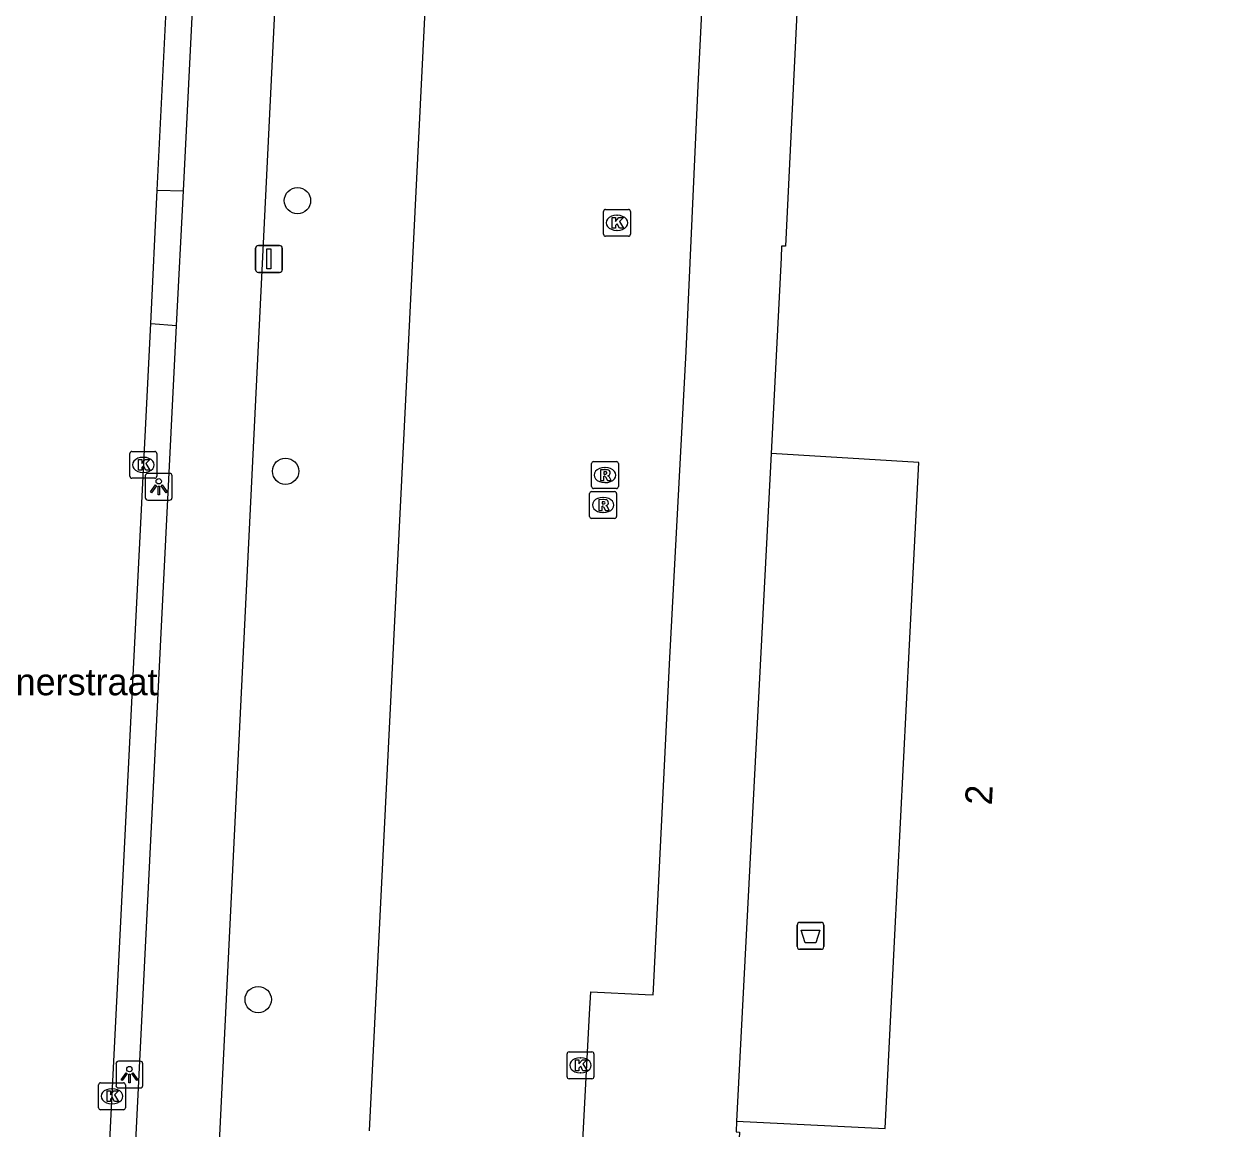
# Model space of a CAD drawing. Extents: x 161761 to 162722, y 384793 to 385405.
# Drawn here: x 162110.58 to 162155.63, y 384928.4 to 384969.48 of the extents above; entities that cross this region are included whole.
import ezdxf

# ---------------------------------------------------------------- set-up
doc = ezdxf.new("R2010")
doc.units = 0
for name, color, linetype in [('IMGEO_Afvalbak', 7, 'Continuous'), ('IMGEO_Boom', 7, 'Continuous'), ('IMGEO_Fietspad_gesloten', 7, 'Continuous'), ('IMGEO_Kolk', 7, 'Continuous'), ('IMGEO_Lichtpunt', 7, 'Continuous'), ('IMGEO_Openbare_ruimte_label', 7, 'Continuous'), ('IMGEO_Pand', 7, 'Continuous'), ('IMGEO_Pand_nummerreeks', 7, 'Continuous'), ('IMGEO_Rijbaan_lokaal_gesloten', 7, 'Continuous'), ('IMGEO_Rijbaan_lokaal_open', 7, 'Continuous'), ('IMGEO_Rioolput', 7, 'Continuous'), ('IMGEO_Verkeersbordpaal', 7, 'Continuous'), ('IMGEO_Verkeerseiland_open', 7, 'Continuous'), ('IMGEO_Voetpad_open', 7, 'Continuous')]:
    doc.layers.add(name, color=color, linetype=linetype)

msp = doc.modelspace()

# ---------------------------------------------------------------- linework, layer by layer
at = {"layer": 'IMGEO_Afvalbak'}
for p, q in [((162139.32, 384935.172), (162139.32, 384935.972)), ((162139.32, 384935.972), (162139.32, 384935.172)), ((162139.42, 384936.072), (162140.21, 384936.072)), ((162140.21, 384936.072), (162139.42, 384936.072)), ((162140.31, 384935.972), (162140.31, 384935.172)), ((162140.31, 384935.172), (162140.31, 384935.972)), ((162140.21, 384935.072), (162139.42, 384935.072)), ((162139.42, 384935.072), (162140.21, 384935.072))]:
    msp.add_line(p, q, dxfattribs=at)
msp.add_lwpolyline([(162139.463, 384935.786), (162140.167, 384935.786), (162140.018, 384935.316), (162139.612, 384935.316), (162139.463, 384935.786)], dxfattribs=at)
for centre, start, end in [((162139.42, 384935.972), 90, 180), ((162139.42, 384935.972), 90, 180), ((162140.21, 384935.972), 0, 90), ((162140.21, 384935.972), 360, 90), ((162139.42, 384935.172), 180, 270), ((162139.42, 384935.172), 180, 270), ((162140.21, 384935.172), 270, 0), ((162140.21, 384935.172), 270, 0)]:
    msp.add_arc(centre, 0.1, start, end, dxfattribs=at)
at = {"layer": 'IMGEO_Boom'}
for centre in [(162120.741, 384962.917), (162120.301, 384952.853), (162119.282, 384933.201)]:
    msp.add_circle(centre, 0.489, dxfattribs=at)
at = {"layer": 'IMGEO_Fietspad_gesloten'}
for points in [[(162116.503, 384963.282), (162118.683, 385007.076)], [(162120.83, 384989.204), (162116.127, 384893.203)], [(162116.239, 384958.276), (162116.503, 384963.282)], [(162112.494, 384887.839), (162113.167, 384887.939), (162113.123, 384894.953), (162113.284, 384898.832), (162116.239, 384958.276)]]:
    msp.add_lwpolyline(points, dxfattribs=at)
at = {"layer": 'IMGEO_Kolk'}
for p, q in [((162132.121, 384961.666), (162132.121, 384962.518)), ((162132.196, 384962.592), (162133.048, 384962.592)), ((162133.122, 384962.518), (162133.122, 384961.666)), ((162132.609, 384962.372), (162132.634, 384962.372)), ((162133.048, 384961.592), (162132.196, 384961.592)), ((162132.632, 384961.812), (162132.607, 384961.812)), ((162114.511, 384952.664), (162114.511, 384953.516)), ((162114.586, 384953.59), (162115.438, 384953.59)), ((162115.512, 384953.516), (162115.512, 384952.664)), ((162114.999, 384953.37), (162115.024, 384953.37)), ((162115.438, 384952.59), (162114.586, 384952.59)), ((162115.022, 384952.81), (162114.997, 384952.81)), ((162130.763, 384930.332), (162130.763, 384931.184)), ((162130.838, 384931.258), (162131.69, 384931.258)), ((162131.251, 384931.038), (162131.276, 384931.038)), ((162131.764, 384931.184), (162131.764, 384930.332)), ((162113.42, 384930.106), (162114.272, 384930.106)), ((162131.69, 384930.258), (162130.838, 384930.258)), ((162131.274, 384930.478), (162131.249, 384930.478)), ((162113.345, 384929.18), (162113.345, 384930.032)), ((162113.833, 384929.886), (162113.858, 384929.886)), ((162114.346, 384930.032), (162114.346, 384929.18)), ((162113.856, 384929.326), (162113.831, 384929.326)), ((162114.272, 384929.106), (162113.42, 384929.106))]:
    msp.add_line(p, q, dxfattribs=at)
for points in [[(162132.121, 384961.666), (162132.121, 384962.518)], [(162132.196, 384962.592), (162133.048, 384962.592)], [(162133.122, 384962.518), (162133.122, 384961.666)], [(162132.442, 384962.292), (162132.565, 384962.292), (162132.565, 384962.141), (162132.695, 384962.292), (162132.859, 384962.292), (162132.713, 384962.141), (162132.866, 384961.892), (162132.714, 384961.892), (162132.629, 384962.056), (162132.565, 384961.989), (162132.565, 384961.892), (162132.442, 384961.892), (162132.442, 384962.292)], [(162133.048, 384961.592), (162132.196, 384961.592)], [(162114.511, 384952.664), (162114.511, 384953.516)], [(162114.586, 384953.59), (162115.438, 384953.59)], [(162115.512, 384953.516), (162115.512, 384952.664)], [(162114.832, 384953.29), (162114.955, 384953.29), (162114.955, 384953.139), (162115.085, 384953.29), (162115.249, 384953.29), (162115.103, 384953.139), (162115.256, 384952.89), (162115.104, 384952.89), (162115.019, 384953.054), (162114.955, 384952.987), (162114.955, 384952.89), (162114.832, 384952.89), (162114.832, 384953.29)], [(162115.438, 384952.59), (162114.586, 384952.59)], [(162130.763, 384930.332), (162130.763, 384931.184)], [(162130.838, 384931.258), (162131.69, 384931.258)], [(162131.084, 384930.958), (162131.207, 384930.958), (162131.207, 384930.807), (162131.337, 384930.958), (162131.501, 384930.958), (162131.355, 384930.807), (162131.508, 384930.558), (162131.356, 384930.558), (162131.271, 384930.722), (162131.207, 384930.655), (162131.207, 384930.558), (162131.084, 384930.558), (162131.084, 384930.958)], [(162131.764, 384931.184), (162131.764, 384930.332)], [(162113.42, 384930.106), (162114.272, 384930.106)], [(162131.69, 384930.258), (162130.838, 384930.258)], [(162113.345, 384929.18), (162113.345, 384930.032)], [(162113.666, 384929.806), (162113.789, 384929.806), (162113.789, 384929.655), (162113.919, 384929.806), (162114.083, 384929.806), (162113.937, 384929.655), (162114.09, 384929.406), (162113.938, 384929.406), (162113.853, 384929.57), (162113.789, 384929.503), (162113.789, 384929.406), (162113.666, 384929.406), (162113.666, 384929.806)], [(162114.346, 384930.032), (162114.346, 384929.18)], [(162114.272, 384929.106), (162113.42, 384929.106)]]:
    msp.add_lwpolyline(points, dxfattribs=at)
for centre, start, end in [((162132.198, 384962.516), 91.552, 178.448), ((162132.198, 384962.516), 91.552, 178.448), ((162133.046, 384962.516), 1.552, 88.448), ((162133.046, 384962.516), 1.552, 88.448), ((162132.198, 384961.668), 181.552, 268.448), ((162132.198, 384961.668), 181.552, 268.448), ((162133.046, 384961.668), 271.552, 358.448), ((162133.046, 384961.668), 271.552, 358.448), ((162114.588, 384953.514), 91.552, 178.448), ((162114.588, 384953.514), 91.552, 178.448), ((162115.436, 384953.514), 1.552, 88.448), ((162115.436, 384953.514), 1.552, 88.448), ((162114.588, 384952.666), 181.552, 268.448), ((162114.588, 384952.666), 181.552, 268.448), ((162115.436, 384952.666), 271.552, 358.448), ((162115.436, 384952.666), 271.552, 358.448), ((162130.84, 384931.182), 91.552, 178.448), ((162130.84, 384931.182), 91.552, 178.448), ((162131.688, 384931.182), 1.552, 88.448), ((162131.688, 384931.182), 1.552, 88.448), ((162113.422, 384930.03), 91.552, 178.448), ((162113.422, 384930.03), 91.552, 178.448), ((162114.27, 384930.03), 1.552, 88.448), ((162114.27, 384930.03), 1.552, 88.448), ((162130.84, 384930.334), 181.552, 268.448), ((162130.84, 384930.334), 181.552, 268.448), ((162131.688, 384930.334), 271.552, 358.448), ((162131.688, 384930.334), 271.552, 358.448), ((162113.422, 384929.182), 181.552, 268.448), ((162113.422, 384929.182), 181.552, 268.448), ((162114.27, 384929.182), 271.552, 358.448), ((162114.27, 384929.182), 271.552, 358.448)]:
    msp.add_arc(centre, 0.0765, start, end, dxfattribs=at)
for centre, major_axis, ratio, start_param, end_param in [((162132.608, 384962.092), (-0.387, 0.002), 0.722429, 4.712389, 7.853982), ((162132.633, 384962.092), (-0.39, 0.002), 0.717154, 1.570796, 4.712389), ((162114.998, 384953.09), (-0.387, 0.002), 0.722429, 4.712389, 7.853982), ((162115.023, 384953.09), (-0.39, 0.002), 0.717154, 1.570796, 4.712389), ((162131.25, 384930.758), (-0.387, 0.002), 0.722429, 4.712389, 7.853982), ((162131.275, 384930.758), (-0.39, 0.002), 0.717154, 1.570796, 4.712389), ((162113.832, 384929.606), (-0.387, 0.002), 0.722429, 4.712389, 7.853982), ((162113.857, 384929.606), (-0.39, 0.002), 0.717154, 1.570796, 4.712389)]:
    msp.add_ellipse(centre, major_axis=major_axis, ratio=ratio, start_param=start_param, end_param=end_param, dxfattribs=at)
at = {"layer": 'IMGEO_Lichtpunt'}
for p, q in [((162115.085, 384952.68), (162115.085, 384951.873)), ((162115.085, 384952.68), (162115.085, 384951.873)), ((162115.987, 384952.775), (162115.179, 384952.775)), ((162115.987, 384952.775), (162115.179, 384952.775)), ((162116.081, 384951.873), (162116.081, 384952.68)), ((162116.081, 384951.873), (162116.081, 384952.68)), ((162115.179, 384951.779), (162115.987, 384951.779)), ((162115.179, 384951.779), (162115.987, 384951.779)), ((162113.995, 384930.818), (162113.995, 384930.011)), ((162113.995, 384930.818), (162113.995, 384930.011)), ((162114.897, 384930.913), (162114.089, 384930.913)), ((162114.897, 384930.913), (162114.089, 384930.913)), ((162114.991, 384930.011), (162114.991, 384930.818)), ((162114.991, 384930.011), (162114.991, 384930.818)), ((162114.089, 384929.917), (162114.897, 384929.917)), ((162114.089, 384929.917), (162114.897, 384929.917))]:
    msp.add_line(p, q, dxfattribs=at)
for points in [[(162115.459, 384952.344), (162115.498, 384952.316), (162115.31, 384952.054), (162115.272, 384952.081), (162115.459, 384952.344)], [(162115.561, 384952.296), (162115.608, 384952.296), (162115.608, 384951.974), (162115.561, 384951.974), (162115.561, 384952.296)], [(162115.671, 384952.316), (162115.709, 384952.343), (162115.896, 384952.081), (162115.857, 384952.053), (162115.671, 384952.316)], [(162114.369, 384930.482), (162114.408, 384930.454), (162114.22, 384930.192), (162114.182, 384930.219), (162114.369, 384930.482)], [(162114.471, 384930.434), (162114.518, 384930.434), (162114.518, 384930.112), (162114.471, 384930.112), (162114.471, 384930.434)], [(162114.581, 384930.454), (162114.619, 384930.481), (162114.806, 384930.219), (162114.767, 384930.191), (162114.581, 384930.454)]]:
    msp.add_lwpolyline(points, dxfattribs=at)
for centre in [(162115.584, 384952.478), (162114.494, 384930.616)]:
    msp.add_circle(centre, 0.0994, dxfattribs=at)
for centre, start, end in [((162115.179, 384952.68), 90, 180), ((162115.179, 384952.68), 90, 180), ((162115.987, 384952.68), 0, 90), ((162115.987, 384952.68), 0, 90), ((162115.179, 384951.873), 180, 270), ((162115.179, 384951.873), 180, 270), ((162115.987, 384951.873), 270, 0), ((162115.987, 384951.873), 270, 360), ((162114.089, 384930.818), 90, 180), ((162114.089, 384930.818), 90, 180), ((162114.897, 384930.818), 0, 90), ((162114.897, 384930.818), 0, 90), ((162114.089, 384930.011), 180, 270), ((162114.089, 384930.011), 180, 270), ((162114.897, 384930.011), 270, 0), ((162114.897, 384930.011), 270, 360)]:
    msp.add_arc(centre, 0.0946, start, end, dxfattribs=at)
at = {"layer": 'IMGEO_Pand'}
for points in [[(162139.461, 384975.555), (162139.42, 384975.018), (162139.56, 384975.011), (162138.881, 384961.219), (162138.741, 384961.226), (162138.719, 384960.786), (162138.35, 384953.517)], [(162137.069, 384928.685), (162142.592, 384928.409), (162142.944, 384935.368), (162143.501, 384946.399), (162143.843, 384953.176), (162138.35, 384953.517)], [(162137.069, 384928.685), (162137.046, 384928.282), (162137.175, 384928.275), (162135.756, 384900.113), (162135.626, 384900.12), (162135.597, 384899.581), (162142.708, 384899.204), (162142.715, 384899.334), (162144.714, 384899.235), (162144.616, 384897.431), (162149.495, 384897.177), (162149.645, 384897.169), (162149.647, 384897.204), (162149.729, 384898.871), (162149.734, 384898.949), (162149.741, 384899.079), (162153.912, 384898.833), (162158.903, 384898.538), (162158.896, 384898.409), (162159.435, 384898.377), (162159.438, 384898.43)]]:
    msp.add_lwpolyline(points, dxfattribs=at)
at = {"layer": 'IMGEO_Rijbaan_lokaal_gesloten'}
for points in [[(162115.526, 384963.307), (162117.175, 384996.297)], [(162115.291, 384958.346), (162115.526, 384963.307)], [(162112.494, 384887.839), (162112.283, 384889.391), (162112.1, 384893.392), (162112.967, 384912.115), (162115.291, 384958.346)]]:
    msp.add_lwpolyline(points, dxfattribs=at)
at = {"layer": 'IMGEO_Rijbaan_lokaal_open'}
for points in [[(162131.352, 384927.951), (162131.603, 384932.665), (162131.646, 384933.486), (162133.673, 384933.388), (162133.971, 384933.373), (162133.982, 384933.595), (162134.57, 384945.679), (162135.188, 384957.302), (162135.639, 384967.205), (162136.14, 384977.124), (162136.726, 384988.375)], [(162138.35, 384953.517), (162137.069, 384928.685)]]:
    msp.add_lwpolyline(points, dxfattribs=at)
at = {"layer": 'IMGEO_Rioolput'}
for p, q in [((162131.674, 384952.284), (162131.674, 384953.136)), ((162131.749, 384953.21), (162132.601, 384953.21)), ((162132.675, 384953.136), (162132.675, 384952.284)), ((162132.162, 384952.99), (162132.187, 384952.99)), ((162132.601, 384952.21), (162131.749, 384952.21)), ((162132.185, 384952.43), (162132.16, 384952.43)), ((162131.604, 384951.171), (162131.604, 384952.023)), ((162131.679, 384952.097), (162132.531, 384952.097)), ((162132.092, 384951.877), (162132.117, 384951.877)), ((162132.605, 384952.023), (162132.605, 384951.171)), ((162132.115, 384951.317), (162132.09, 384951.317)), ((162132.531, 384951.097), (162131.679, 384951.097))]:
    msp.add_line(p, q, dxfattribs=at)
for points in [[(162131.674, 384952.284), (162131.674, 384953.136)], [(162131.749, 384953.21), (162132.601, 384953.21)], [(162132.675, 384953.136), (162132.675, 384952.284)], [(162132.263, 384952.908), (162132.011, 384952.91), (162132.011, 384952.51)], [(162132.011, 384952.51), (162132.135, 384952.51), (162132.135, 384952.672), (162132.146, 384952.672)], [(162132.189, 384952.829), (162132.135, 384952.829), (162132.135, 384952.748)], [(162132.135, 384952.748), (162132.187, 384952.748)], [(162132.193, 384952.643), (162132.264, 384952.51), (162132.404, 384952.51), (162132.339, 384952.636)], [(162132.601, 384952.21), (162131.749, 384952.21)], [(162131.604, 384951.171), (162131.604, 384952.023)], [(162131.679, 384952.097), (162132.531, 384952.097)], [(162132.193, 384951.795), (162131.941, 384951.797), (162131.941, 384951.397)], [(162132.119, 384951.716), (162132.065, 384951.716), (162132.065, 384951.635)], [(162132.605, 384952.023), (162132.605, 384951.171)], [(162131.941, 384951.397), (162132.065, 384951.397), (162132.065, 384951.559), (162132.076, 384951.559)], [(162132.065, 384951.635), (162132.117, 384951.635)], [(162132.123, 384951.53), (162132.194, 384951.397), (162132.334, 384951.397), (162132.269, 384951.523)], [(162132.531, 384951.097), (162131.679, 384951.097)]]:
    msp.add_lwpolyline(points, dxfattribs=at)
for centre, radius, start, end in [((162131.751, 384953.134), 0.0765, 91.552, 178.448), ((162131.751, 384953.134), 0.0765, 91.552, 178.448), ((162132.599, 384953.134), 0.0765, 1.552, 88.448), ((162132.599, 384953.134), 0.0765, 1.552, 88.448), ((162132.145, 384952.619), 0.0533, 26.0293, 88.6989), ((162132.171, 384952.937), 0.19, 274.7715, 282.9687), ((162132.195, 384952.733), 0.0964, 77.0061, 93.1865), ((162132.209, 384952.79), 0.0378, 276.6634, 79.6772), ((162132.262, 384952.798), 0.109, 350.3612, 89.416), ((162132.26, 384952.798), 0.112, 277.5842, 350.9817), ((162132.244, 384952.583), 0.108, 29.5134, 73.7905), ((162131.751, 384952.286), 0.0765, 181.552, 268.448), ((162131.751, 384952.286), 0.0765, 181.552, 268.448), ((162132.599, 384952.286), 0.0765, 271.552, 358.448), ((162132.599, 384952.286), 0.0765, 271.552, 358.448), ((162131.681, 384952.021), 0.0765, 91.552, 178.448), ((162131.681, 384952.021), 0.0765, 91.552, 178.448), ((162132.125, 384951.62), 0.0964, 77.0061, 93.1865), ((162132.139, 384951.677), 0.0378, 276.6634, 79.6772), ((162132.192, 384951.685), 0.109, 350.3612, 89.416), ((162132.19, 384951.685), 0.112, 277.5842, 350.9817), ((162132.529, 384952.021), 0.0765, 1.552, 88.448), ((162132.529, 384952.021), 0.0765, 1.552, 88.448), ((162132.075, 384951.506), 0.0533, 26.0293, 88.6989), ((162132.101, 384951.824), 0.19, 274.7715, 282.9687), ((162132.174, 384951.47), 0.108, 29.5134, 73.7905), ((162131.681, 384951.173), 0.0765, 181.552, 268.448), ((162131.681, 384951.173), 0.0765, 181.552, 268.448), ((162132.529, 384951.173), 0.0765, 271.552, 358.448), ((162132.529, 384951.173), 0.0765, 271.552, 358.448)]:
    msp.add_arc(centre, radius, start, end, dxfattribs=at)
for centre, major_axis, ratio, start_param, end_param in [((162132.161, 384952.71), (-0.387, 0.002), 0.722429, 4.712389, 7.853982), ((162132.186, 384952.71), (-0.39, 0.002), 0.717154, 1.570796, 4.712389), ((162132.091, 384951.597), (-0.387, 0.002), 0.722429, 4.712389, 7.853982), ((162132.116, 384951.597), (-0.39, 0.002), 0.717154, 1.570796, 4.712389)]:
    msp.add_ellipse(centre, major_axis=major_axis, ratio=ratio, start_param=start_param, end_param=end_param, dxfattribs=at)
at = {"layer": 'IMGEO_Verkeersbordpaal'}
for p, q in [((162119.187, 384960.35), (162119.187, 384961.15)), ((162119.187, 384961.15), (162119.187, 384960.35)), ((162119.287, 384961.25), (162120.077, 384961.25)), ((162120.077, 384961.25), (162119.287, 384961.25)), ((162120.177, 384961.15), (162120.177, 384960.35)), ((162120.177, 384960.35), (162120.177, 384961.15)), ((162120.077, 384960.25), (162119.287, 384960.25)), ((162119.287, 384960.25), (162120.077, 384960.25))]:
    msp.add_line(p, q, dxfattribs=at)
msp.add_lwpolyline([(162119.607, 384961.125), (162119.757, 384961.125), (162119.757, 384960.375), (162119.607, 384960.375), (162119.607, 384961.125)], dxfattribs=at)
for centre, start, end in [((162119.287, 384961.15), 90, 180), ((162119.287, 384961.15), 90, 180), ((162120.077, 384961.15), 0, 90), ((162120.077, 384961.15), 360, 90), ((162119.287, 384960.35), 180, 270), ((162119.287, 384960.35), 180, 270), ((162120.077, 384960.35), 270, 0), ((162120.077, 384960.35), 270, 0)]:
    msp.add_arc(centre, 0.1, start, end, dxfattribs=at)
at = {"layer": 'IMGEO_Verkeerseiland_open'}
for points in [[(162115.526, 384963.307), (162116.503, 384963.282)], [(162115.291, 384958.346), (162116.239, 384958.276)]]:
    msp.add_lwpolyline(points, dxfattribs=at)
at = {"layer": 'IMGEO_Voetpad_open'}
msp.add_lwpolyline([(162126.113, 384982.723), (162123.403, 384928.319)], dxfattribs=at)

# ---------------------------------------------------------------- texts
at = {"layer": 'IMGEO_Openbare_ruimte_label'}
msp.add_text('Ds Theodor Fliednerstraat', height=1, dxfattribs=at).set_placement((162100.007, 384944.52))
at = {"layer": 'IMGEO_Pand_nummerreeks'}
msp.add_text('2', height=1, rotation=87.1984, dxfattribs=at).set_placement((162146.557, 384940.417))

doc.saveas('drawing.dxf')
